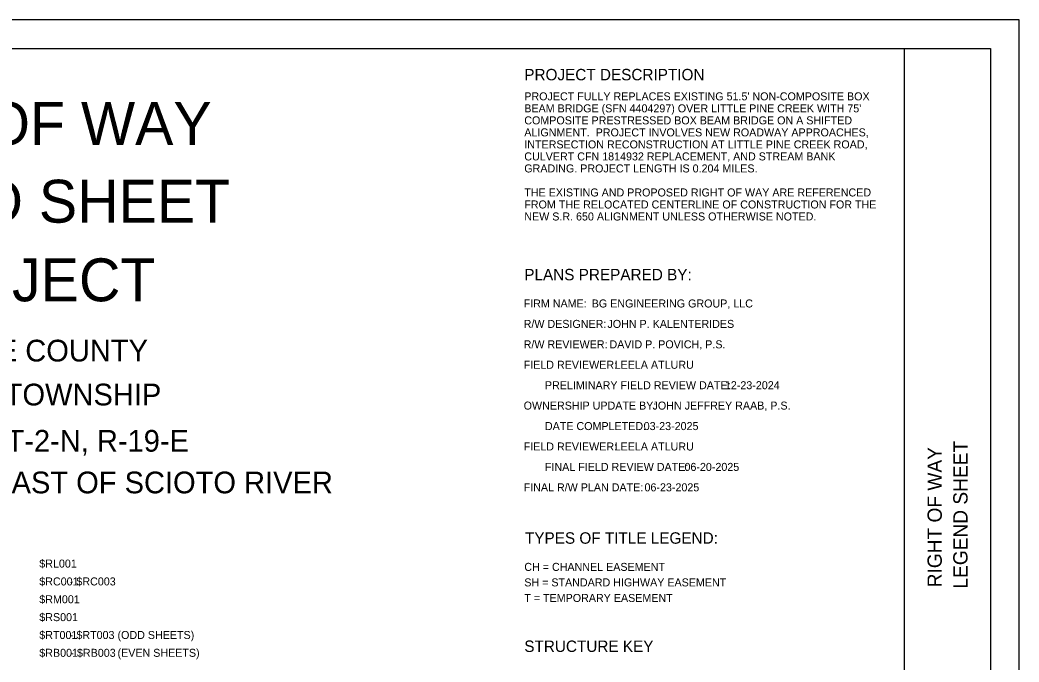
# Model space of a CAD drawing. Extents: x 0 to 34, y 0 to 22.
# Drawn here: x 16.53 to 34, y 10.78 to 22 of the extents above; entities that cross this region are included whole.
import ezdxf

# ---------------------------------------------------------------- set-up
doc = ezdxf.new("R2010")
doc.units = 0
for name, color, linetype in [('SH_Border', 7, 'Continuous'), ('SH_Cut_Line', 7, 'Continuous'), ('SH_Data', 7, 'Continuous'), ('SH_Text', 7, 'Continuous')]:
    doc.layers.add(name, color=color, linetype=linetype)

msp = doc.modelspace()

# ---------------------------------------------------------------- linework, layer by layer
at = {"layer": 'SH_Border'}
msp.add_line((32, 0.5), (32, 21.5), dxfattribs=at)
msp.add_lwpolyline([(1.5, 21.5), (33.5, 21.5), (33.5, 0.5), (1.5, 0.5)], close=True, dxfattribs=at)
at = {"layer": 'SH_Cut_Line'}
msp.add_lwpolyline([(0, 0), (34, 0), (34, 22), (0, 22)], close=True, dxfattribs=at)

# ---------------------------------------------------------------- texts
at = {"layer": 'SH_Data'}
for s, height, p in [('RIGHT OF WAY', 0.75, (12.527, 19.816)), ('LEGEND SHEET', 0.75, (12.458, 18.457)), ('$PROJECT', 0.75, (13.66, 17.082)), ('LAWRENCE COUNTY', 0.38, (13.602, 16.03)), ('ELIZABETH TOWNSHIP', 0.38, (13.355, 15.262)), (' SEC. 15, T-2-N, R-19-E', 0.38, (13.979, 14.453)), ('   CONGRESS LANDS EAST OF SCIOTO RIVER  ', 0.38, (10.736, 13.725)), ('$RL001', 0.14, (16.868, 12.427)), ('$RC001', 0.14, (16.868, 12.115)), ('$RC003', 0.14, (17.517, 12.115)), ('-', 0.14, (17.4, 12.115)), ('$RM001', 0.14, (16.868, 11.803)), ('$RS001', 0.14, (16.868, 11.491)), ('$RT001', 0.14, (16.868, 11.179)), ('-', 0.14, (17.4, 11.179)), ('$RT003', 0.14, (17.517, 11.179)), ('(ODD SHEETS)', 0.14, (18.236, 11.179)), ('$RB001', 0.14, (16.868, 10.867)), ('$RB003', 0.14, (17.527, 10.867)), ('(EVEN SHEETS)', 0.14, (18.236, 10.867)), ('-', 0.14, (17.41, 10.867))]:
    msp.add_text(s, height=height, dxfattribs=at).set_placement(p)
for s, p in [('RIGHT OF WAY', (32.65, 12.082)), ('LEGEND SHEET', (33.1, 12.06))]:
    msp.add_text(s, height=0.25, rotation=90, dxfattribs=at).set_placement(p)
at = {"layer": 'SH_Text'}
for s, height, p in [('PROJECT DESCRIPTION', 0.2, (25.349, 20.945)), ("PROJECT FULLY REPLACES EXISTING 51.5' NON-COMPOSITE BOX ", 0.14, (25.349, 20.595)), ("BEAM BRIDGE (SFN 4404297) OVER LITTLE PINE CREEK WITH 75' ", 0.14, (25.349, 20.385)), ('COMPOSITE PRESTRESSED BOX BEAM BRIDGE ON A SHIFTED ', 0.14, (25.349, 20.175)), ('ALIGNMENT.  PROJECT INVOLVES NEW ROADWAY APPROACHES, ', 0.14, (25.349, 19.965)), ('INTERSECTION RECONSTRUCTION AT LITTLE PINE CREEK ROAD, ', 0.14, (25.349, 19.755)), ('CULVERT CFN 1814932 REPLACEMENT, AND STREAM BANK ', 0.14, (25.349, 19.545)), ('GRADING. PROJECT LENGTH IS 0.204 MILES.', 0.14, (25.349, 19.335)), ('THE EXISTING AND PROPOSED RIGHT OF WAY ARE REFERENCED ', 0.14, (25.349, 18.915)), ('FROM THE RELOCATED CENTERLINE OF CONSTRUCTION FOR THE ', 0.14, (25.349, 18.705)), ('NEW S.R. 650 ALIGNMENT UNLESS OTHERWISE NOTED.', 0.14, (25.349, 18.495)), ('PLANS PREPARED BY:', 0.2, (25.349, 17.449)), ('FIRM NAME: ', 0.14, (25.338, 16.974)), ('BG ENGINEERING GROUP, LLC', 0.14, (26.528, 16.974)), ('R/W DESIGNER: ', 0.14, (25.338, 16.617)), ('JOHN P. KALENTERIDES', 0.14, (26.803, 16.617)), ('R/W REVIEWER: ', 0.14, (25.338, 16.26)), ('DAVID P. POVICH, P.S.', 0.14, (26.838, 16.26)), ('FIELD REVIEWER: ', 0.14, (25.338, 15.903)), ('LEELA ATLURU', 0.14, (26.929, 15.903)), ('PRELIMINARY FIELD REVIEW DATE: ', 0.14, (25.71, 15.545)), ('12-23-2024', 0.14, (28.857, 15.545)), ('OWNERSHIP UPDATE BY: ', 0.14, (25.338, 15.189)), ('JOHN JEFFREY RAAB, P.S.', 0.14, (27.591, 15.189)), ('DATE COMPLETED: ', 0.14, (25.71, 14.831)), ('03-23-2025', 0.14, (27.437, 14.831)), ('FIELD REVIEWER: ', 0.14, (25.338, 14.474)), ('LEELA ATLURU', 0.14, (26.929, 14.474)), ('FINAL FIELD REVIEW DATE: ', 0.14, (25.71, 14.117)), ('06-20-2025', 0.14, (28.15, 14.117)), ('FINAL R/W PLAN DATE: ', 0.14, (25.338, 13.76)), ('06-23-2025', 0.14, (27.451, 13.76)), ('TYPES OF TITLE LEGEND:', 0.2, (25.361, 12.844)), ('CH = CHANNEL EASEMENT', 0.14, (25.349, 12.369)), ('SH = STANDARD HIGHWAY EASEMENT', 0.14, (25.349, 12.098)), ('T = TEMPORARY EASEMENT', 0.14, (25.349, 11.826)), ('STRUCTURE KEY', 0.2, (25.349, 10.952))]:
    msp.add_text(s, height=height, dxfattribs=at).set_placement(p)

doc.saveas('drawing.dxf')
